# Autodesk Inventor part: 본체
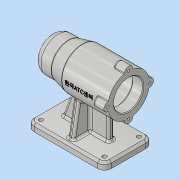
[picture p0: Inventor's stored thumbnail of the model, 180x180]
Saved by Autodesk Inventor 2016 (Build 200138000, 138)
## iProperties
Created: 2019-07
Part Number: 본체
Material: 알루미늄 6061
Document SubType Name: Modeling
Designer: Administrator
Density: 2.7 g/cm^3
Appearance: 알루미늄 - 평지
Mass: 644.388 g
Surface Area: 654.094 cm^2
Volume: 238.662 cm^3
Author: Administrator
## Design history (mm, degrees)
sketch "스케치2"
  geometry: L1 (56, 0)-(-56, 0); L2 (-56, 0)-(-56, 30); L3 (-56, 30)-(11, 30); L4 (11, 30)-(31, 25); L5 (31, 25)-(56, 25); L6 (56, 25)-(56, 0); 2 further points
  constraints: 12 end point, 3 perpendicular, 1 coincident, 1 horizontal, 1 midpoint, 1 parallel
  dimensions: "d0" = 60 diameter of L3 L1; "d1" = 50 diameter of L5 L1; "d2" = 25 distance of L4.end L5.end; "d3" = 67 distance of L2.end L3.end; "d4" = 112 distance between parallel lines of L2 L6
revolve "회전1" sketch "스케치2" stored, may be unused: angle "d5" = 90 deg
node "작업 평면1"
sketch "스케치4"
  geometry: L1 (56, 30)-(56, -30) reference; L2 (-56, 35)-(56, 35); L3 (56, 35)-(56, -35); L4 (56, -35)-(-56, -35); L5 (-56, -35)-(-56, 35); 2 further points
  constraints: 8 end point, 2 midpoint, 2 parallel, 1 collinear, 1 horizontal, 1 perpendicular
  dimensions: "d11" = 112 distance of L2.start L2.end; "d12" = 70 distance of L4.end L2.start
extrude "돌출1" join sketch "스케치4" distance "d13" = 10; taper "d14" = 0 deg
sketch "스케치5"
  geometry: L1 (31, -25)-(56, -25) reference; L2 (11, -30)-(31, -25) reference; L3 (-56, -30)-(11, -30) reference; L4 (-56, -70)-(56, -70) reference; L5 (20.57, -27.607)-(36, -70); L6 (-31, -30)-(-31, -70); L7 (-56, -80)-(-56, -70) reference; L8 (56, -80)-(56, -70) reference; L9 (36, -70)-(-31, -70); 1 further point
  constraints: 6 end point, 4 point on line, 1 horizontal, 1 perpendicular
  dimensions: "d15" = 25 distance between parallel lines of L7 L6; "d16" = 20 distance from line of L8 L5.end; "d17" = 110 deg angle of L4 L5
feature "리브1" sketch "스케치5" dims "d18" = 1, "d19" = 8, "d20" = 0, "d21" = 0, "d22" = 1, "d23" = 1
sketch "스케치9"
  geometry: L1 (35, -70)-(-35, -70) reference; L2 (4, -27.341)-(4, -70) reference; L3 (-4, -70)-(-4, -27.341) reference; L4 (-19.654, -22.666)-(-28, -70); L5 (19.654, -22.666)-(28, -70); L6 (35, -80)-(35, -70) reference; L7 (-35, -80)-(-35, -70) reference; L8 (-28, -70)-(28, -70); A1 r 30 centre (0, 0) between (4, -29.732) and (-4, -29.732) reference; 1 further point
  constraints: 6 end point, 2 point on circle, 2 point on line, 1 collinear
  dimensions: "d34" = 7 distance from line of L6 L5.end; "d35" = 7 distance from line of L7 L4.end; "d36" = 100 deg angle of L1 L4; "d37" = 100 deg angle of L1 L5
feature "리브3" sketch "스케치9" dims "d38" = 1, "d39" = 8, "d40" = 0, "d41" = 0, "d42" = 1, "d43" = 1
sketch "스케치10"
  geometry: C1 r 21 at (0, 0); 1 further point
  constraints: 1 centre point, 1 coincident
  dimensions: "d44" = 42 diameter of C1
extrude "돌출2" cut sketch "스케치10" distance "d45" = 15; taper "d46" = 0 deg
sketch "스케치11"
  geometry: C1 r 24 at (0, 0); 1 further point
  constraints: 1 centre point, 1 coincident
  dimensions: "d47" = 48 diameter of C1
extrude "돌출3" cut sketch "스케치11" distance "d48" = 54; taper "d49" = 0 deg
sketch "스케치12"
  geometry: C1 r 21 at (0, 0); 1 further point
  constraints: 1 centre point, 1 coincident
  dimensions: "d50" = 42 diameter of C1
extrude "돌출4" cut sketch "스케치12" distance "d51" = 12; taper "d52" = 0 deg
sketch "스케치13"
  geometry: C1 r 17.5 at (0, 0); 1 further point
  constraints: 1 centre point, 1 coincident
  dimensions: "d53" = 35 diameter of C1
extrude "돌출5" cut sketch "스케치13" distance "d54" = 18; taper "d55" = 0 deg
sketch "스케치14"
  geometry: C1 r 16 at (0, 0); 1 further point
  constraints: 1 centre point, 1 coincident
  dimensions: "d56" = 32 diameter of C1
extrude "돌출6" cut sketch "스케치14" distance "d57" = 4; taper "d58" = 0 deg
sketch "스케치15"
  geometry: C1 r 10.5 at (0, 0); 1 further point
  constraints: 1 centre point, 1 coincident
  dimensions: "d59" = 21 diameter of C1
extrude "돌출7" cut sketch "스케치15" distance "d60" = 3; taper "d61" = 0 deg
sketch "스케치16"
  geometry: A1 r 30 centre (0, 0) between (-30, 0) and (-29.4, -5.97) reference; A2 r 6 centre (-30, 0) between (-29.4, 5.97) and (-29.4, -5.97); 1 further point
  constraints: 5 point on circle, 1 centre point, 1 horizontal alignment
  dimensions: "d62" = 6 radius of A2
extrude "돌출8" join sketch "스케치16" distance "d63" = 16; taper "d64" = 0 deg
sketch "스케치17"
  geometry: A1 r 6 centre (0, 0) between (0.6, 5.97) and (0.6, -5.97) reference; A2 r 6 centre (30, -30) between (24.03, -29.4) and (35.97, -29.4) reference; A3 r 6 centre (60, 0) between (59.4, -5.97) and (59.4, 5.97) reference; A4 r 6 centre (30, 30) between (35.97, 29.4) and (24.03, 29.4) reference; 5 further points
  constraints: 4 coincident
hole "구멍1" sketch "스케치17" at (0, 0), (30, -30), (60, 0), (30, 30) diameter "d68" = 3.242; stored, may be unused: countersink angle "d72" = 90 deg, drill point angle "d74" = 118 deg; dims "d69" = 8, "d70" = 4, "d71" = 2, "d73" = 11
fillet "모깎기1" dims "d75" = 10
sketch "스케치18"
  geometry: A1 r 10 centre (-46, 25) between (-46, 35) and (-56, 25) reference; A2 r 10 centre (-46, -25) between (-56, -25) and (-46, -35) reference; A3 r 10 centre (46, -25) between (46, -35) and (56, -25) reference; A4 r 10 centre (46, 25) between (56, 25) and (46, 35) reference; 5 further points
  constraints: 4 coincident
hole "구멍2" sketch "스케치18" at (-46, 25), (46, 25), (46, -25), (-46, -25) diameter "d76" = 6; stored, may be unused: countersink angle "d80" = 90 deg, drill point angle "d82" = 118 deg; dims "d77" = 8, "d78" = 4, "d79" = 2, "d81" = 11
chamfer "모따기1" distance "d83" = 3; stored, may be unused: second distance "d84" = 2, angle "d85" = 45 deg
chamfer "모따기2" distance "d86" = 1; stored, may be unused: second distance "d87" = 2, angle "d88" = 45 deg
fillet "모깎기2" dims "d89" = 3, "d90" = 0.3
fillet "모깎기3" dims "d91" = 10, "d92" = 3
fillet "모깎기4" dims "d93" = 1
fillet "모깎기5" dims "d94" = 3
node "작업 평면2"
sketch "스케치19"
  geometry: L1 (33.5, 29.226)-(33.5, 6.771) reference; L2 (33.5, -5.998)-(33.5, 5.998) reference; L3 (33.5, -6.771)-(33.5, -29.226) reference; 3 further points
  constraints: 1 horizontal alignment, 1 midpoint, 1 other
  dimensions: "d95" = 42 distance from line of L1 point (-8.5, 0)
feature "엠보싱1" sketch "스케치19" dims "d96" = 0.5, "d97" = 0
node "솔리드1"
pattern_circular "원형 패턴1" dims angle "d66" = 360 deg
